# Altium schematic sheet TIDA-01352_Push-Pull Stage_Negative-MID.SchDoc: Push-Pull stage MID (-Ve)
size 431 x 279 mm; Date: Not shown in title block; ApprovedBy: Not shown in title block; CheckedBy: Not shown in title block; Author: Not shown in title block; CompanyName: Not shown in title block; DrawnBy: Sanjay Pithadia; Engineer: Sanjay Pithadia; Organization: Not shown in title block; Address1: Not shown in title block; Address2: Not shown in title block; Address3: Not shown in title block; Address4: Not shown in title block; DocumentNumber: 1; Revision: Use project parameter SCH_Rev; SheetNumber: 8; SheetTotal: 9; PageSetup: Record=PageOptions¦CenterHorizontal=True¦CenterVertical=True¦PrintScale=1.00¦XCorrection=1.00¦YCorrection=1.00¦PrintKind=0¦BorderSize=5000000¦LeftOffset=0¦BottomOffset=0¦Orientation=2¦PaperLength=1000¦PaperWidth=1000¦Scale=100¦PaperSource=15¦PrintQuality=600¦MediaType=1¦DitherType=10¦PaperKind=Letter¦PrintScaleMode=1
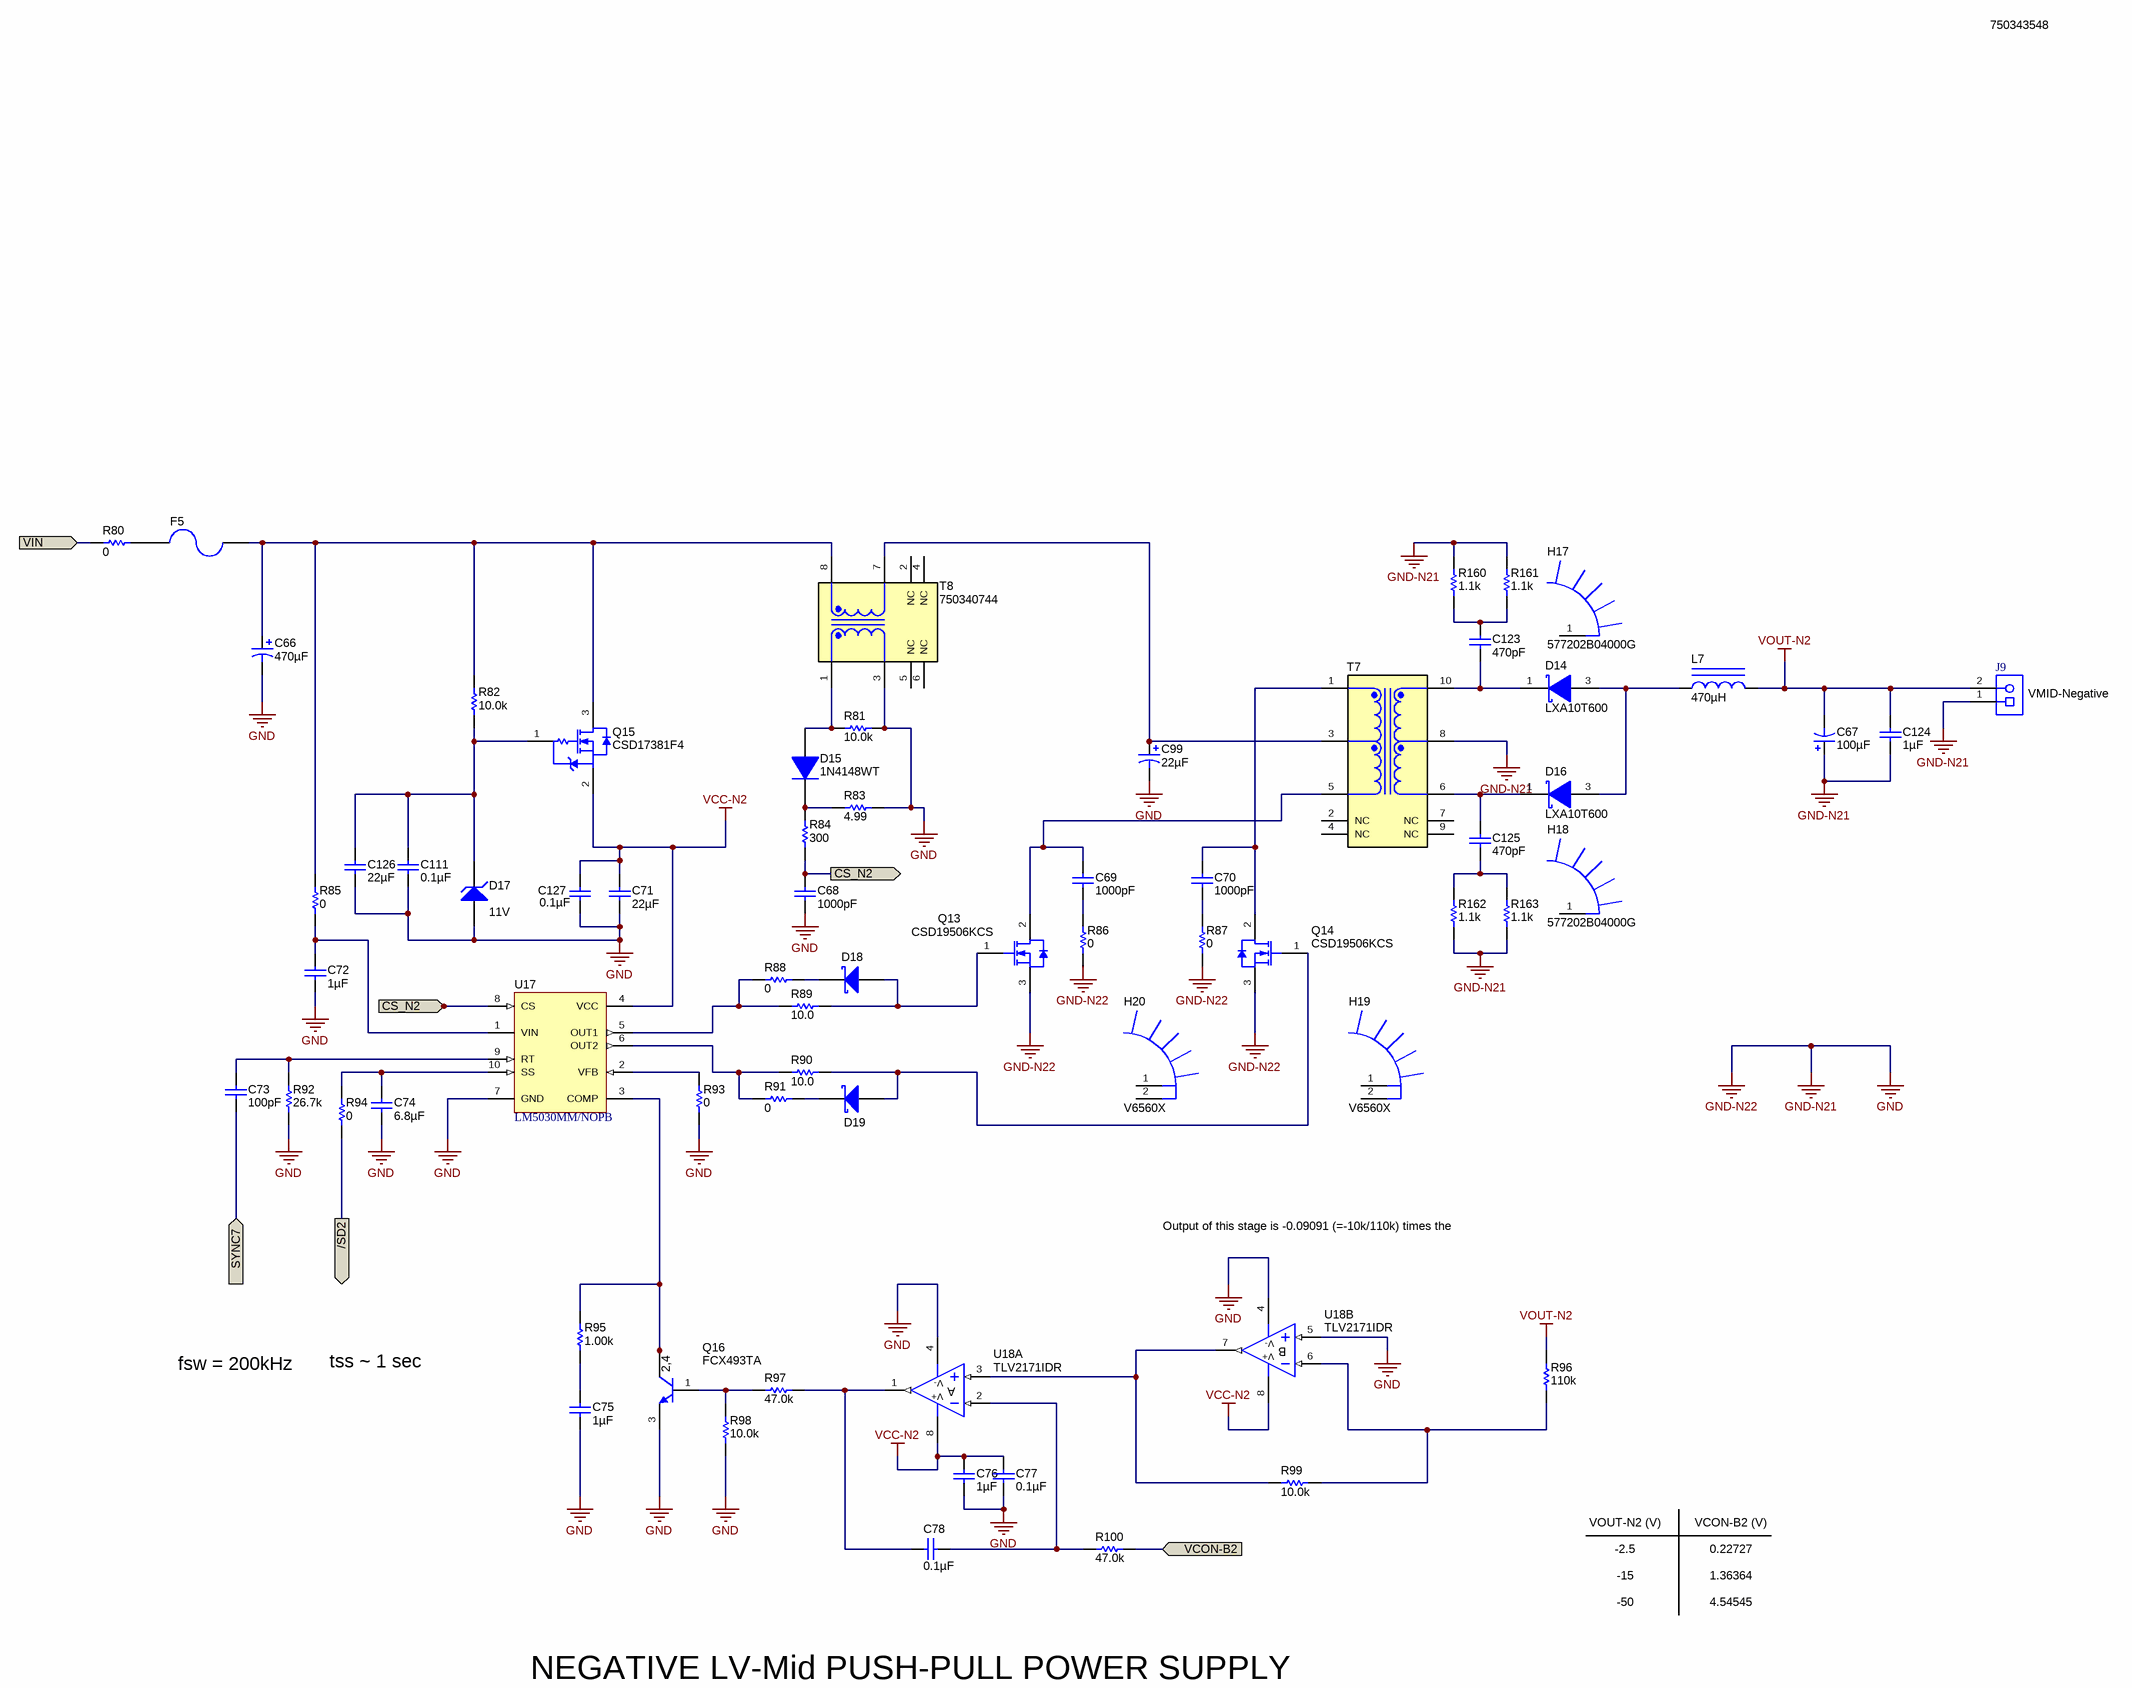
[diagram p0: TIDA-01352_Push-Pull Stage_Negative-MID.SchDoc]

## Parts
C66  ValueDisplayed: 470µF  [WCAP-ATLI_1300x3000]  (hidden comment: 860080778023)
C67  ValueDisplayed: 100µF  [Nichicon_2000x3000_Snap]  (hidden comment: LLS2G101MELY)
C68  ValueDisplayed: 1000pF  [0603]  (hidden comment: GRM188R71E102KA01D)
C69  ValueDisplayed: 1000pF  [0603]  (hidden comment: GRM188R71E102KA01D)
C70  ValueDisplayed: 1000pF  [0603]  (hidden comment: GRM188R71E102KA01D)
C71  ValueDisplayed: 22µF  [1210_280]  (hidden comment: 12103D226MAT2A)
C72  ValueDisplayed: 1µF  [0805_HV]  (hidden comment: 08055C105KAT2A)
C73  ValueDisplayed: 100pF  [0603]  (hidden comment: 06035A101FAT2A)
C74  ValueDisplayed: 6.8µF  [0603]  (hidden comment: C1608X5R1E685K080AC)
C75  ValueDisplayed: 1µF  [0603]  (hidden comment: GMK107BJ105KA-T)
C76  ValueDisplayed: 1µF  [0805_HV]  (hidden comment: 08055C105KAT2A)
C77  ValueDisplayed: 0.1µF  [0603]  (hidden comment: 06035C104KAT2A)
C78  ValueDisplayed: 0.1µF  [0603]  (hidden comment: 06035C104KAT2A)
C99  ValueDisplayed: 22µF  [SM_RADIAL_E]  (hidden comment: EEE-FC1H220P)
C111  ValueDisplayed: 0.1µF  [0603]  (hidden comment: 06035C104KAT2A)
C123  ValueDisplayed: 470pF  [1206]  (hidden comment: VJ1206Y471KBEAT4X)
C124  ValueDisplayed: 1µF  [2220_200]  (hidden comment: GRM55DR72E105KW01L)
C125  ValueDisplayed: 470pF  [1206]  (hidden comment: VJ1206Y471KBEAT4X)
C126  ValueDisplayed: 22µF  [1210_280]  (hidden comment: 12103D226MAT2A)
C127  ValueDisplayed: 0.1µF  [0603]  (hidden comment: 06035C104KAT2A)
D14  LXA10T600  [TO-220AC]
D15  1N4148WT  [Fairchild_SOD-523F]
D16  LXA10T600  [TO-220AC]
D17  value 11V  [SMA]  (hidden comment: 1SMA5926BT3G)
D18  PMEG1030EJ,115  [SOD-323F]  (value not drawn)
D19  PMEG1030EJ,115  [SOD-323F]  (value not drawn)
F5  0679L9100-01  [Fuse_SSQ]  (value not drawn)
H17  577202B04000G  [Aavid_577202B04000G]
H18  577202B04000G  [Aavid_577202B04000G]
H19  V6560X  [ASMN_V6560X]
H20  V6560X  [ASMN_V6560X]
J9  1727010  [PhoenixConact_1727010]  (value not drawn)
L7  ValueDisplayed: 470µH  [1447440C]  (hidden comment: 1447440C)
Q13  CSD19506KCS  [KCS0003B]
Q14  CSD19506KCS  [KCS0003B]
Q15  CSD17381F4  [YJC0003A]
Q16  FCX493TA  [SOT-89-3]
R80  ValueDisplayed: 0  [5108]  (hidden comment: 5108)
R81  ValueDisplayed: 10.0k  [0603]  (hidden comment: CRCW060310K0FKEA)
R82  ValueDisplayed: 10.0k  [0603]  (hidden comment: CRCW060310K0FKEA)
R83  ValueDisplayed: 4.99  [0805_HV]  (hidden comment: CRCW08054R99FKEA)
R84  ValueDisplayed: 300  [0603]  (hidden comment: RC0603FR-07300RL)
R85  ValueDisplayed: 0  [0603]  (hidden comment: CRCW06030000Z0EA)
R86  ValueDisplayed: 0  [0603]  (hidden comment: CRCW06030000Z0EA)
R87  ValueDisplayed: 0  [0603]  (hidden comment: CRCW06030000Z0EA)
R88  ValueDisplayed: 0  [0603]  (hidden comment: CRCW06030000Z0EA)
R89  ValueDisplayed: 10.0  [0603]  (hidden comment: CRCW060310R0FKEA)
R90  ValueDisplayed: 10.0  [0603]  (hidden comment: CRCW060310R0FKEA)
R91  ValueDisplayed: 0  [0603]  (hidden comment: CRCW06030000Z0EA)
R92  ValueDisplayed: 26.7k  [0603]  (hidden comment: CRCW060326K7FKEA)
R93  ValueDisplayed: 0  [0603]  (hidden comment: CRCW06030000Z0EA)
R94  ValueDisplayed: 0  [0603]  (hidden comment: CRCW06030000Z0EA)
R95  ValueDisplayed: 1.00k  [0603]  (hidden comment: CRCW06031K00FKEA)
R96  ValueDisplayed: 110k  [1206]  (hidden comment: CRCW1206110KFKEA)
R97  ValueDisplayed: 47.0k  [0603]  (hidden comment: RC0603FR-0747KL)
R98  ValueDisplayed: 10.0k  [0603]  (hidden comment: CRCW060310K0FKEA)
R99  ValueDisplayed: 10.0k  [1206]  (hidden comment: CRCW120610K0FKEA)
R100  ValueDisplayed: 47.0k  [0603]  (hidden comment: RC0603FR-0747KL)
R160  ValueDisplayed: 1.1k  [PR01]  (hidden comment: PR01000101101JR500)
R161  ValueDisplayed: 1.1k  [PR01]  (hidden comment: PR01000101101JR500)
R162  ValueDisplayed: 1.1k  [PR01]  (hidden comment: PR01000101101JR500)
R163  ValueDisplayed: 1.1k  [PR01]  (hidden comment: PR01000101101JR500)
T7  750343548  [Wurth_750343473]
T8  750340744  [Wurth_750340744]
U17  LM5030MM/NOPB  [MUB10A_N]
U18  TLV2171IDR  [D0008A_N]  (parts A,B of 2)

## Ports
/SD2 (out), CS_N2 (in), CS_N2 (out), SYNC7 (in), VCON-B2 (in), VIN (in)

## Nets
GND: C66.2(-) C67.1(+) C68.2 C71.2 C72.2 C74.2 C75.2 C76.2 C77.2 C99.2(-) C111.2 C124.2 C126.2 C127.2 D17.2(A) J9.1 Q13.3(S) Q14.3(S) Q16.3(E) R81.1 R83.2 R86.2 R87.2 R92.1 R93.1 R98.1 R160.2 R161.2 R162.1 R163.1 T7.8 T8.3 U17.7(GND) U18.4(V-) U18.5(IN+)  [also labelled GND-N21, GND-N22]
VCC-N2: C71.1 C76.1 C77.1 C127.1 Q15.2(S) U17.4(VCC) U18.8(V+)
VOUT-N2: C67.2(-) C124.1 J9.2 L7.2 R96.2
/SD2: R94.1 ; port /SD2
CS_N2: C68.1 R84.1 U17.8(CS) ; port CS_N2
SYNC7: C73.2 ; port SYNC7
VCON-B2: R100.2 ; port VCON-B2
VIN: R80.1 ; port VIN
NetC66_1: C66.1(+) F5.1 Q15.3(D) R82.2 R85.2 T8.8
NetC69_1: C69.1 Q13.2(D) T7.5
NetC69_2: C69.2 R86.1
NetC70_1: C70.1 Q14.2(D) T7.1
NetC70_2: C70.2 R87.1
NetC72_1: C72.1 R85.1 U17.1(VIN)
NetC73_1: C73.1 R92.2 U17.9(RT)
NetC74_1: C74.1 R94.2 U17.10(SS)
NetC75_1: C75.1 R95.1
NetC78_1: C78.1 R100.1 U18.2(IN-)
NetC78_2: C78.2 R97.2 U18.1(OUT)
NetC99_1: C99.1(+) T7.3 T8.7
NetC111_1: C111.1 C126.1 D17.1(K) Q15.1(G) R82.1
NetC123_1: C123.1 R160.1 R161.1
NetC123_2: C123.2 D14.1(A) T7.10
NetC125_1: C125.1 D16.1(A) T7.6
NetC125_2: C125.2 R162.2 R163.2
NetD14_3: D14.3(K) D16.3(K) L7.1
NetD15_1: D15.1(K) R83.1 R84.2
NetD15_2: D15.2(A) R81.2 T8.1
NetD18_1: D18.1(K) R88.1
NetD18_2: D18.2(A) Q13.1(G) R89.2
NetD19_1: D19.1(K) R91.1
NetD19_2: D19.2(A) Q14.1(G) R90.2
NetF5_2: F5.2 R80.2
NetQ16_1: Q16.1(B) R97.1 R98.2
NetQ16_2: Q16.2(C) Q16.4(C) R95.2 U17.3(COMP)
NetR88_2: R88.2 R89.1 U17.5(OUT1)
NetR90_1: R90.1 R91.2 U17.6(OUT2)
NetR93_2: R93.2 U17.2(VFB)
NetR96_1: R96.1 R99.1 U18.6(IN-)
NetR99_2: R99.2 U18.3(IN+) U18.7(OUT)

Not connected (* = marked no-connect by the designer): H17 1; H18 1; H19 1 2; H20 1 2; T7 2(NC) 4(NC) 7(NC) 9(NC); T8 2(NC) 4(NC) 5(NC) 6(NC)

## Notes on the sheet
- (near J9) VMID-Negative
- Output of this stage is -0.09091 (=-10k/110k) times the VOUT-N2
- fsw = 200kHz
- tss ~ 1 sec
- VOUT-N2 (V)
- VCON-B2 (V)
- -2.5
- -15
- 0.22727
- 1.36364
- -50
- 4.54545
- NEGATIVE LV-Mid PUSH-PULL POWER SUPPLY

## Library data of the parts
C66 = 860080778023: CAP, AL, 470 µF, 63 V, +/- 20%, TH; Manufacturer: Wurth Elektronik; Polarized: Y; CompType: Capacitor; Value: 470uF; U/M: EA; Cap_F: 0.00047; Tolerance_%: 20; Value1: Unknown; VDC_V: 63; Value2: 63V; IRMS_A: 2.225; TaMin_C: -55; TaMax_C: 105; Cap_Case: 13x30mm; SizeAreaWB_mm2: 225; SizeArea_mm2: 169; SizeX_mm: 13; SizeZ_mm: 31.5; AEC Category: Q200; AEC Qualified: N
C67 = LLS2G101MELY: CAP, AL, 100 µF, 400 V, +/- 20%, TH; Manufacturer: Nichicon; Polarized: Y; CompType: Capacitor; Value: 100uF; U/M: EA; Cap_F: 0.0001; Tolerance_%: 20; Value1: Unknown; VDC_V: 400; Value2: 400V; IRMS_A: 0.95; TaMin_C: -25; TaMax_C: 85; Cap_Case: 20x30mm; SizeAreaWB_mm2: 484; SizeZ_mm: 32; AEC Category: Q200; AEC Qualified: N
C68-C70 = GRM188R71E102KA01D: CAP, CERM, 1000 pF, 25 V, +/- 10%, X7R, 0603; Manufacturer: MuRata; Polarized: N; CompType: Capacitor; Value: 1000pF; U/M: EA; Cap_F: 0.000000001; Tolerance_%: 10; Value1: Unknown; VDC_V: 25; Value2: 25V; TaMin_C: -55; TaMax_C: 125; SizeArea_mm2: 1.28; SizeAreaWB_mm2: 4.68; SizeX_mm: 1.6; SizeY_mm: 0.8; SizeZ_mm: 1; AEC Category: Q200
C71 C126 = 12103D226MAT2A: CAP, CERM, 22 µF, 25 V, +/- 20%, X5R, 1210; Manufacturer: AVX; Polarized: N; CompType: Capacitor; Value: 22uF; U/M: EA; Cap_F: 0.000022; Tolerance_%: 20; Value1: Unknown; VDC_V: 25; Value2: 25V; TaMin_C: -55; TaMax_C: 85; Cap_Case: 1210; SizeArea_mm2: 8; SizeAreaWB_mm2: 14.7; SizeX_mm: 3.2; SizeY_mm: 2.5; SizeZ_mm: 2.8; AEC Category: Q200
C72 C76 = 08055C105KAT2A: CAP, CERM, 1 µF, 50 V, +/- 10%, X7R, 0805; Manufacturer: AVX; Polarized: N; CompType: Capacitor; Value: 1uF; U/M: EA; Cap_F: 0.000001; Tolerance_%: 10; Value1: Unknown; VDC_V: 50; Value2: 50V; TaMin_C: -55; TaMax_C: 125; Cap_Case: 0805; SizeArea_mm2: 2.5; SizeAreaWB_mm2: 6.75; SizeX_mm: 2; SizeY_mm: 1.25; SizeZ_mm: 1.45; AEC Category: Q200
C73 = 06035A101FAT2A: CAP, CERM, 100 pF, 50 V, +/- 1%, C0G/NP0, 0603; Manufacturer: AVX; Polarized: N; CompType: Capacitor; Value: 100pF; U/M: EA; Cap_F: 0.0000000001; Tolerance_%: 1; Value1: Unknown; VDC_V: 50; Value2: 50V; TaMin_C: -55; TaMax_C: 125; SizeArea_mm2: 1.28; SizeAreaWB_mm2: 4.68; SizeX_mm: 1.6; SizeY_mm: 0.8; AEC Category: Q200
C74 = C1608X5R1E685K080AC: CAP, CERM, 6.8 µF, 25 V, +/- 10%, X5R, 0603; Manufacturer: TDK; Polarized: N; CompType: Capacitor; Value: 6.8uF; U/M: EA; Cap_F: 0.0000068; Tolerance_%: 10; ESR_ohm: 0.004211; Value1: 0.004211 ohm; VDC_V: 25; Value2: 25V; IRMS_A: 2.534067; TaMin_C: -55; TaMax_C: 85; SizeArea_mm2: 1.28; SizeAreaWB_mm2: 4.68; SizeX_mm: 1.6; SizeY_mm: 0.8; SizeZ_mm: 1; AEC Category: Q200
C75 = GMK107BJ105KA-T: CAP, CERM, 1 µF, 35 V, +/- 10%, X5R, 0603; Manufacturer: Taiyo Yuden; Polarized: N; CompType: Capacitor; Value: 1uF; U/M: EA; Cap_F: 0.000001; Tolerance_%: 10; Value1: Unknown; VDC_V: 35; Value2: 35V; TaMin_C: -55; TaMax_C: 85; SizeArea_mm2: 1.28; SizeAreaWB_mm2: 4.68; SizeX_mm: 1.6; SizeY_mm: 0.8; SizeZ_mm: 1; AEC Category: Q200
C77 C78 C111 C127 = 06035C104KAT2A: CAP, CERM, 0.1 µF, 50 V, +/- 10%, X7R, 0603; Manufacturer: AVX; Polarized: N; CompType: Capacitor; Value: 0.1uF; U/M: EA; Cap_F: 0.0000001; Tolerance_%: 10; Value1: Unknown; VDC_V: 50; Value2: 50V; TaMin_C: -55; TaMax_C: 125; SizeArea_mm2: 1.28; SizeAreaWB_mm2: 4.68; SizeX_mm: 1.6; SizeY_mm: 0.8; SizeZ_mm: 1; AEC Category: Q200
C99 = EEE-FC1H220P: CAP, AL, 22 µF, 50 V, +/- 20%, 0.7 ohm, SMD; Manufacturer: Panasonic; Polarized: Y; CompType: Capacitor; Value: 22uF; U/M: EA; Cap_F: 0.000022; Tolerance_%: 20; Value1: 0.7 ohm; VDC_V: 50; Value2: 50V; ESR_ohm: 0.7; IRMS_A: 0.12; TaMin_C: -40; TaMax_C: 105; Cap_Case: E; SizeAreaWB_mm2: 118.45; SizeArea_mm2: 78.85; SizeX_mm: 9.5; SizeY_mm: 8.3; SizeZ_mm: 6.2; AEC Category: Q200
C123 C125 = VJ1206Y471KBEAT4X: CAP, CERM, 470 pF, 500 V, +/- 10%, X7R, 1206; Manufacturer: Vishay-Vitramon; Polarized: N; CompType: Capacitor; Value: 470pF; U/M: EA; Cap_F: 0.00000000047; Tolerance_%: 10; Value1: Unknown; VDC_V: 500; Value2: 500V; TaMin_C: -55; TaMax_C: 125; SizeArea_mm2: 5.12; SizeAreaWB_mm2: 10.92; SizeX_mm: 3.2; SizeY_mm: 1.6; SizeZ_mm: 1.35; AEC Category: Q200
C124 = GRM55DR72E105KW01L: CAP, CERM, 1 µF, 250 V, +/- 10%, X7R, 2220; Manufacturer: MuRata; Polarized: N; CompType: Capacitor; Value: 1uF; U/M: EA; Cap_F: 0.000001; Tolerance_%: 10; ESR_ohm: 0.007086; Value1: 0.007086 ohm; VDC_V: 250; Value2: 250V; IRMS_A: 2.0605; TaMin_C: -55; TaMax_C: 125; Cap_Case: 2220; SizeArea_mm2: 28.5; SizeAreaWB_mm2: 53.9; SizeX_mm: 5.7; SizeY_mm: 5; SizeZ_mm: 2; AEC Category: Q200
D14 D16 = LXA10T600: Diode, Schottky, 600 V, 10 A, TH; Manufacturer: Power Integrations; SymbolCreator: a0412235; U/M: EA; Vf_V: 2.4; Value: 600V; Value1: 10A; Value2: 2.4V; Io_A: 10; Vr_V: 600; TJmax_C: 150; RJC_CperW: 1.4; SizeAreaWB_mm2: 78.975; SizeArea_mm2: 45.675; SizeX_mm: 10.15; SizeY_mm: 4.5; SizeZ_mm: 23; AEC Category: Q101; AEC Qualified: N
D15 = 1N4148WT: Diode, Switching, 75 V, 0.3 A, SOD-523F; Manufacturer: Fairchild Semiconductor; U/M: EA; Value: 75V; Value1: 0.3A; Io_A: 0.3; Vr_V: 75; TJmax_C: 150; SizeAreaWB_mm2: 4.68; SizeArea_mm2: 1.28; SizeX_mm: 1.6; SizeY_mm: 0.8; SizeZ_mm: 0.7; AEC Category: Q101
D17 = 1SMA5926BT3G: Diode, Zener, 11 V, 1.5 W, SMA; Manufacturer: ON Semiconductor; SymbolCreator: a0412235; U/M: EA; Power_W: 1.5; Vz_V: 11; Value1: 1.5W; RJA_CperW: 250; SizeAreaWB_mm2: 37.3428; SizeArea_mm2: 16.3228; SizeX_mm: 5.59; SizeY_mm: 2.92; SizeZ_mm: 2.87; AEC Category: Q101
D18 D19 = PMEG1030EJ,115: Diode, Schottky, 10 V, 3 A, SOD-323F; Manufacturer: NXP Semiconductor; U/M: EA; Vf_V: 0.53; Value: 10V; Value1: 3A; Value2: 0.53V; Io_A: 3; Vr_V: 10; TJmax_C: 150; SizeAreaWB_mm2: 7.875; SizeArea_mm2: 3.125; SizeX_mm: 2.5; SizeY_mm: 1.25; SizeZ_mm: 0.8; AEC Category: Q101; AEC Qualified: N
F5 = SSQ 8: FUSE BRD MNT 10A 125VAC/VDC; Manufacturer: Bel Fuse; VDC_V: 125; Interrupt_AC: 50; Irating_A: 8; Rtyp_Ohm: 0.008; MeltingTyp: 26
H17 H18 = 577202B04000G: HEATSINK TO-220 .500" COMPACT; Manufacturer: Aavid; SymbolCreator: a0412235
H19 H20 = V6560X: HEATSINK, ALUM, ANOD, for TO-220; Manufacturer: Assman WSW; SymbolCreator: a0799628
J9 = 1727010: Conn Term Block, 2POS, 3.81mm, TH; Manufacturer: Phoenix Contact; SymbolCreator: a0412235; CompType: Terminal Block
L7 = 1447440C: Inductor, Wirewound, 470 µH, 4 A, 0.125 ohm, TH; Manufacturer: MuRata; Value: 470uH; Ind_H: 470.0E-6; Imax_A: 4; Irms: 4A @ 50C rise; Isat: 4A @ 40% inductance drop; DCR_ohm: 0.125; Value2: 4A; SizeAreaWB_mm2: 1071.66; SizeArea_mm2: 944.66; SizeX_mm: 31.7; SizeY_mm: 29.8; SizeZ_mm: 23.5; AEC Category: Q200; AEC Qualified: N
Q13 Q14 = CSD19506KCS: MOSFET, N-CH, 80 V, 100 A, KCS0003B (TO-220-3); Manufacturer: Texas Instruments; Alternate Manufacturer: None; U/M: EA; ChType: N; Value: 80V; VdsMax_V: 80; Value1: ? ohm; Value2: 120 nC; QgTyp_nC: 120; Vgs_V: 20; IdsMax_A: 100; SizeAreaWB_mm2: 79.648; SizeArea_mm2: 46.228; SizeX_mm: 4.55; SizeY_mm: 10.16; SizeZ_mm: 20.45; AEC Category: Q101
Q15 = CSD17381F4: MOSFET, N-CH, 30 V, 3.1 A, YJC0003A (PICOSTAR-3); Manufacturer: Texas Instruments; Alternate Manufacturer: None; SymbolCreator: a0411947; U/M: EA; ChType: N; Value: 30V; VdsMax_V: 30; Value1: 0.09 ohm; Rdson45_ohm: 0.09; Value2: 1.04 nC; QgTyp_nC: 1.04; Vgs_V: 12; IdsMax_A: 3.1; SizeAreaWB_mm2: 3.327225; SizeArea_mm2: 0.657225; SizeX_mm: 1.035; SizeY_mm: 0.635; SizeZ_mm: 0.35; AEC Category: Q101
Q16 = FCX493TA, Diodes Inc.: Transistor, NPN, 100 V, 1 A, SOT-89; SymbolCreator: a0412235; PNP: 0; NPN: 1; Vceo_V: 100; Vcesat1_V: 0.6; Value: 100 V; Value1: 1 A; HfeMax: 300; TaMin_C: -65; TaMax_C: 150; CompType: BJT; U/M: EA; AEC Category: Q101; SizeAreaWB_mm2: 28.05; SizeArea_mm2: 18.45; SizeX_mm: 4.1; SizeY_mm: 4.5; SizeZ_mm: 1.5
R80 = 5108: RES, 0, 1%, 0.5 W, 1206; Manufacturer: Keystone; CompType: Resistor; Value: 0; Tolerance_%: 1; Power_W: 0.5; Value2: 0.5W; TempCo: ppm/C; SizeArea_mm2: 5.185; SizeX_mm: 3.05; SizeY_mm: 1.7; SizeZ_mm: 0.84; U/M: EA; AEC Category: Q200; AEC Qualified: N
R81 R82 R98 = CRCW060310K0FKEA: RES, 10.0 k, 1%, 0.1 W, 0603; Manufacturer: Vishay-Dale; CompType: Resistor; Value: 10.0k; Res_ohm: 10000; Value_Code: 10k0; Tolerance_%: 1; Power_W: 0.1; Value2: 0.1W; VDC_V: 75; TempCo: 100 ppm/C; SizeArea_mm2: 1.28; SizeX_mm: 1.6; SizeY_mm: 0.8; EIA_Code: E96; U/M: EA; AEC Category: Q200
R83 = CRCW08054R99FKEA: RES, 4.99, 1%, 0.125 W, 0805; Manufacturer: Vishay-Dale; CompType: Resistor; Value: 4.99; Value_Code: 4R99; Tolerance_%: 1; Power_W: 0.125; Value2: 0.125W; VDC_V: 150; TempCo: 100 ppm/C; SizeArea_mm2: 2.5; SizeX_mm: 2; SizeY_mm: 1.25; SizeZ_mm: 1.45; EIA_Code: E96; U/M: EA; AEC Category: Q200
R84 = RC0603FR-07300RL: RES, 300, 1%, 0.1 W, 0603; Manufacturer: Yageo America; CompType: Resistor; Value: 300; Value_Code: 300R; Tolerance_%: 1; Power_W: 0.1; Value2: 0.1W; VDC_V: 150; TempCo: 200 ppm/C; SizeArea_mm2: 1.28; SizeX_mm: 1.6; SizeY_mm: 0.8; U/M: EA; AEC Category: Q200
R85-R88 R91 R93 R94 = CRCW06030000Z0EA: RES, 0, 5%, 0.1 W, 0603; Manufacturer: Vishay-Dale; CompType: Resistor; Value: 0; Value_Code: 0000; Tolerance_%: 5; Power_W: 0.1; Value2: 0.1W; VDC_V: 75; TempCo: 200 ppm/C; SizeArea_mm2: 1.28; SizeX_mm: 1.6; SizeY_mm: 0.8; SizeZ_mm: 1; EIA_Code: E24; U/M: EA; AEC Category: Q200
R89 R90 = CRCW060310R0FKEA: RES, 10.0, 1%, 0.1 W, 0603; Manufacturer: Vishay-Dale; CompType: Resistor; Value: 10.0; Res_ohm: 10; Value_Code: 10R0; Tolerance_%: 1; Power_W: 0.1; Value2: 0.1W; VDC_V: 75; TempCo: 100 ppm/C; SizeArea_mm2: 1.28; SizeX_mm: 1.6; SizeY_mm: 0.8; EIA_Code: E96; U/M: EA; AEC Category: Q200
R92 = CRCW060326K7FKEA: RES, 26.7 k, 1%, 0.1 W, 0603; Manufacturer: Vishay-Dale; CompType: Resistor; Value: 26.7k; Res_ohm: 26700; Value_Code: 26k7; Tolerance_%: 1; Power_W: 0.1; Value2: 0.1W; VDC_V: 75; TempCo: 100 ppm/C; SizeArea_mm2: 1.28; SizeX_mm: 1.6; SizeY_mm: 0.8; EIA_Code: E96; U/M: EA; AEC Category: Q200
R95 = CRCW06031K00FKEA: RES, 1.00 k, 1%, 0.1 W, 0603; Manufacturer: Vishay-Dale; CompType: Resistor; Value: 1.00k; Res_ohm: 1000; Value_Code: 1k00; Tolerance_%: 1; Power_W: 0.1; Value2: 0.1W; VDC_V: 75; TempCo: 100 ppm/C; SizeArea_mm2: 1.28; SizeX_mm: 1.6; SizeY_mm: 0.8; EIA_Code: E96; U/M: EA; AEC Category: Q200
R96 = CRCW1206110KFKEA: RES, 110 k, 1%, 0.25 W, 1206; Manufacturer: Vishay-Dale; CompType: Resistor; Value: 110k; Res_ohm: 110000; Tolerance_%: 1; Power_W: 0.25; Value2: 0.25W; VDC_V: 200; TempCo: 100 ppm/C; SizeArea_mm2: 5.12; SizeX_mm: 3.2; SizeY_mm: 1.6; SizeZ_mm: 1.35; EIA_Code: E96; U/M: EA; AEC Category: Q200
R97 R100 = RC0603FR-0747KL: RES, 47.0 k, 1%, 0.1 W, 0603; Manufacturer: Yageo America; CompType: Resistor; Value: 47.0k; Res_ohm: 47000; Value_Code: 47k0; Tolerance_%: 1; Power_W: 0.1; Value2: 0.1W; VDC_V: 150; TempCo: 200 ppm/C; SizeArea_mm2: 1.28; SizeX_mm: 1.6; SizeY_mm: 0.8; U/M: EA; AEC Category: Q200
R99 = CRCW120610K0FKEA: RES, 10.0 k, 1%, 0.25 W, 1206; Manufacturer: Vishay-Dale; CompType: Resistor; Value: 10.0k; Res_ohm: 10000; Value_Code: 10k0; Tolerance_%: 1; Power_W: 0.25; Value2: 0.25W; VDC_V: 200; TempCo: 100 ppm/C; SizeArea_mm2: 5.12; SizeX_mm: 3.2; SizeY_mm: 1.6; SizeZ_mm: 1.35; EIA_Code: E96; U/M: EA; AEC Category: Q200
R160-R163 = PR01000101101JR500: RES, 1.1 k, 5%, 1 W, AEC-Q200 Grade 0, D2.5xL6.5mm; Manufacturer: Vishay-Bccomponents; CompType: Resistor; Value: 1.1k; Res_ohm: 1100; Value_Code: 1k10; Tolerance_%: 5; Power_W: 1; Value2: 1W; VDC_V: 350; TempCo: 250 ppm/C; EIA_Code: E24; U/M: EA; AEC Category: Q200; AEC Qualified: Y; AEC Grade: 0
T7 = 750343548: Transformer, 100 uH, TH; Manufacturer: Wurth Elektronik; SymbolCreator: Altium; ValueDisplayed: 100µH; Value: 100uH; DCR_ohm: 0.025; Lp: 100; Ind_H: 0.0001; Ns1toNp: 3; Rsec1_ohm: 0.058; Rsec2_ohm: 0.08; SizeAreaWB_mm2: 934.4274; SizeArea_mm2: 816.1274; SizeX_mm: 29.21; SizeY_mm: 27.94; SizeZ_mm: 21.59
T8 = 750340744: Transformer, TH; Manufacturer: Wurth Elektronik; SymbolCreator: Altium; ValueDisplayed: 2mH; Value: 2mH; Lp: 2000; Ns1toNp: 100; Rs1: 5.87; SizeAreaWB_mm2: 94.9181; SizeArea_mm2: 59.9181; SizeX_mm: 8.13; SizeY_mm: 7.37; SizeZ_mm: 5.46
U17 = LM5030MM/NOPB: 100V Push-Pull Current Mode PWM Controller, 10-pin MSOP, Pb-Free; Manufacturer: Texas Instruments; PackageTopMarking: ZXTT*S73B; PowerWise: Y; CompType: Switcher
U18 = TLV2171IDR: 36-V, Single-Supply, Low-Power Operational Amplifier for Cost-Sensitive Systems, D0008A (SOIC-8); Manufacturer: Texas Instruments; CompType: IC; SizeArea_mm2: 30.38; SizeAreaWB_mm2: 56.58; SizeX_mm: 4.9; SizeY_mm: 6.2; SizeZ_mm: 1.75; U/M: EA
